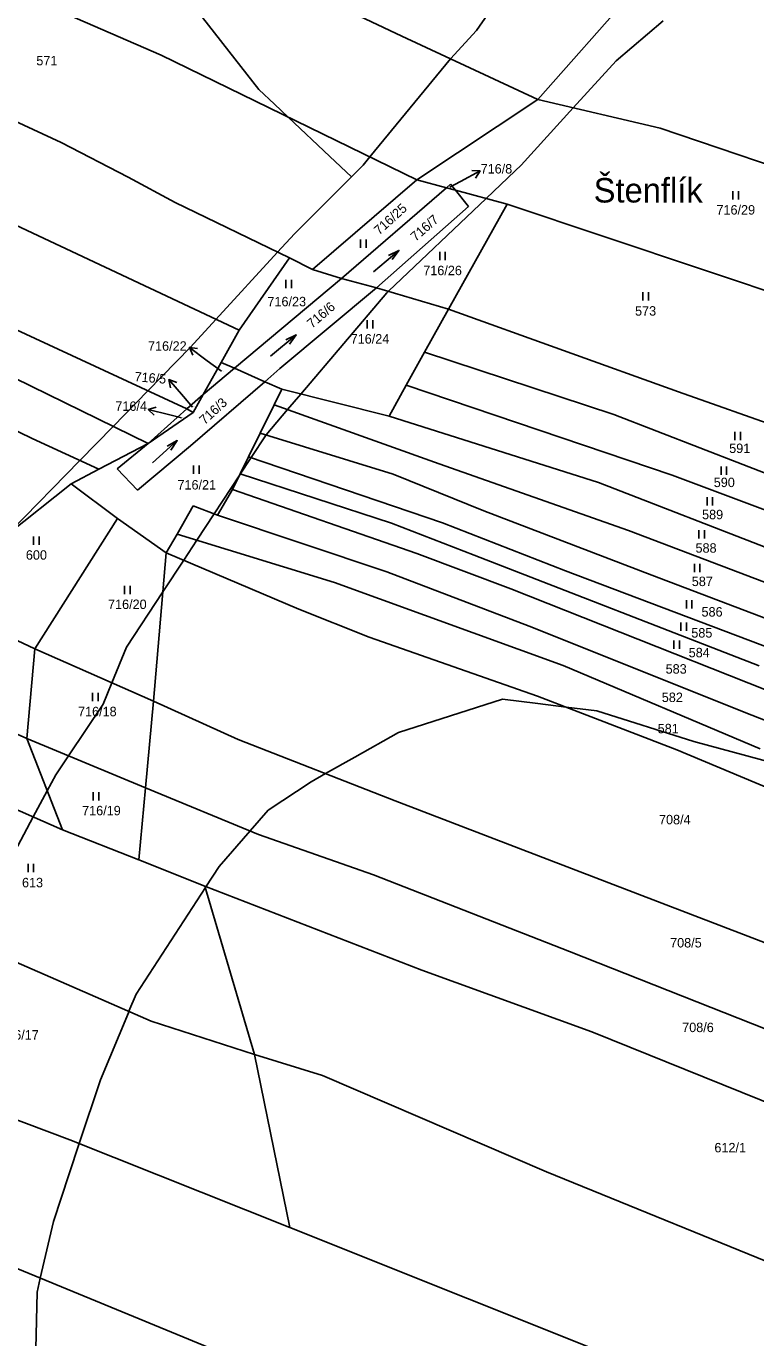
# Model space of a CAD drawing. Extents: x -749173 to -746119, y -1132678 to -1130338.
# Drawn here: x -748430.5 to -748299.2, y -1131207.1 to -1130971 of the extents above; entities that cross this region are included whole.
import ezdxf

# ---------------------------------------------------------------- set-up
doc = ezdxf.new("R2010")
doc.units = 0
for name, color, linetype in [('Vrstva 1', 7, 'Continuous'), ('Vrstva 15', 7, 'Continuous'), ('Vrstva 16', 7, 'Continuous'), ('Vrstva 18', 7, 'Continuous'), ('Vrstva 25', 7, 'Continuous'), ('Vrstva 52', 7, 'Continuous'), ('Vrstva 6', 7, 'Continuous')]:
    doc.layers.add(name, color=color, linetype=linetype)

msp = doc.modelspace()

# ---------------------------------------------------------------- linework, layer by layer
at = {"layer": 'Vrstva 1'}
for points in [[(-748321.33, -1130964.79), (-748338.46, -1130984.21)], [(-748338.46, -1130984.21), (-748360.19, -1130998.63)], [(-748360.19, -1130998.63), (-748379, -1131014.81)], [(-748354.9, -1131000.06), (-748354.14, -1130999.4)], [(-748354.14, -1130999.4), (-748353.27, -1131000.5)], [(-748373.77, -1131016.38), (-748354.9, -1131000.06)], [(-748353.27, -1131000.5), (-748350.94, -1131003.46)], [(-748350.94, -1131003.46), (-748367.47, -1131018.07)], [(-748383.15, -1131012.7), (-748392.16, -1131025.73)], [(-748379, -1131014.81), (-748383.15, -1131012.7)], [(-748393.03, -1131032.57), (-748373.77, -1131016.38)], [(-748367.47, -1131018.07), (-748384.84, -1131032.61)], [(-748358.83, -1131029.64), (-748354.54, -1131021.9)], [(-748354.54, -1131021.9), (-748313.1, -1131036.82)], [(-748392.16, -1131025.73), (-748395.42, -1131031.51)], [(-748362.13, -1131035.6), (-748358.83, -1131029.64)], [(-748395.42, -1131031.51), (-748398.67, -1131037.3)], [(-748398.67, -1131037.3), (-748393.03, -1131032.57)], [(-748384.84, -1131032.61), (-748387.58, -1131034.98)], [(-748401.59, -1131039.86), (-748398.67, -1131037.3)], [(-748387.58, -1131034.98), (-748400.96, -1131046.55)], [(-748385.87, -1131039.12), (-748384.5, -1131036.34)], [(-748384.5, -1131036.34), (-748365.22, -1131041.21)], [(-748365.22, -1131041.21), (-748362.13, -1131035.6)], [(-748313.1, -1131036.82), (-748275.09, -1131050.22)], [(-748388.38, -1131044.22), (-748385.87, -1131039.12)], [(-748408.58, -1131046.09), (-748401.59, -1131039.86)], [(-748390.49, -1131048.5), (-748388.38, -1131044.22)], [(-748417.45, -1131050.74), (-748408.58, -1131046.09)], [(-748414.17, -1131050.66), (-748408.58, -1131046.09)], [(-748400.96, -1131046.55), (-748410.47, -1131054.51)], [(-748392.02, -1131051.59), (-748390.49, -1131048.5)], [(-748422.44, -1131053.36), (-748417.45, -1131050.74)], [(-748410.47, -1131054.51), (-748414.17, -1131050.66)], [(-748433.86, -1131062.5), (-748422.44, -1131053.36)], [(-748393.4, -1131054.38), (-748392.02, -1131051.59)], [(-748393.4, -1131054.38), (-748396.09, -1131058.99)], [(-748360.23, -1131065.88), (-748393.4, -1131054.38)], [(-748400.45, -1131057.32), (-748403.37, -1131062.41)], [(-748396.09, -1131058.99), (-748400.45, -1131057.32)], [(-748403.37, -1131062.41), (-748405.3, -1131065.79)], [(-748405.3, -1131065.79), (-748407.59, -1131092.49)], [(-748343.3, -1131072.28), (-748360.23, -1131065.88)], [(-748277.63, -1131098.3), (-748343.3, -1131072.28)], [(-748407.59, -1131092.49), (-748409.03, -1131108.09)], [(-748409.03, -1131108.09), (-748410.22, -1131121.04)], [(-748410.22, -1131121.04), (-748398.34, -1131125.81)], [(-748398.34, -1131125.81), (-748389.42, -1131156.09)], [(-748389.42, -1131156.09), (-748383.08, -1131187.24)], [(-748422.65, -1131171.45), (-748446.57, -1131162.45)], [(-748383.08, -1131187.24), (-748422.65, -1131171.45)]]:
    msp.add_lwpolyline(points, dxfattribs=at)
at = {"layer": 'Vrstva 16'}
for p, q in [((-748350.34, -1130996.99), (-748348.84, -1130997.04)), ((-748400.55, -1131030.19), (-748401.15, -1131028.81)), ((-748404.55, -1131036.08), (-748404.83, -1131034.61)), ((-748407.46, -1131041.03), (-748408.54, -1131039.99))]:
    msp.add_line(p, q, dxfattribs=at)
for points in [[(-748352.37, -1130998.93), (-748348.84, -1130997.04), (-748349.64, -1130998.32)], [(-748354.3, -1130999.96), (-748352.37, -1130998.93)], [(-748397.94, -1131031.2), (-748401.15, -1131028.81), (-748399.66, -1131028.98)], [(-748395.38, -1131033.11), (-748397.94, -1131031.2)], [(-748402.22, -1131037.64), (-748404.83, -1131034.61), (-748403.41, -1131035.1)], [(-748404.66, -1131040.96), (-748408.54, -1131039.99), (-748407.1, -1131039.58)], [(-748400.57, -1131039.56), (-748402.22, -1131037.64)], [(-748402.56, -1131041.48), (-748404.66, -1131040.96)]]:
    msp.add_lwpolyline(points, dxfattribs=at)
at = {"layer": 'Vrstva 25'}
for p, q in [((-748303.33, -1131000.7), (-748303.33, -1131002.2)), ((-748302.33, -1131002.2), (-748302.33, -1131000.7)), ((-748370.35, -1131009.4), (-748370.35, -1131010.9)), ((-748369.35, -1131010.9), (-748369.35, -1131009.4)), ((-748368.04, -1131015.2), (-748363.44, -1131011.34)), ((-748356.1, -1131011.61), (-748356.1, -1131013.11)), ((-748355.1, -1131013.11), (-748355.1, -1131011.61)), ((-748383.76, -1131016.66), (-748383.76, -1131018.16)), ((-748382.76, -1131018.16), (-748382.76, -1131016.66)), ((-748319.53, -1131018.89), (-748319.53, -1131020.39)), ((-748318.53, -1131020.39), (-748318.53, -1131018.89)), ((-748369.16, -1131023.92), (-748369.16, -1131025.42)), ((-748368.16, -1131025.42), (-748368.16, -1131023.92)), ((-748386.53, -1131030.38), (-748381.93, -1131026.54)), ((-748302.98, -1131044), (-748302.98, -1131045.5)), ((-748301.98, -1131045.5), (-748301.98, -1131044)), ((-748407.8, -1131049.61), (-748403.34, -1131045.59)), ((-748400.39, -1131050.06), (-748400.39, -1131051.56)), ((-748399.39, -1131051.56), (-748399.39, -1131050.06)), ((-748305.46, -1131050.24), (-748305.46, -1131051.74)), ((-748304.46, -1131051.74), (-748304.46, -1131050.24)), ((-748307.98, -1131055.79), (-748307.98, -1131057.29)), ((-748306.98, -1131057.29), (-748306.98, -1131055.79)), ((-748429.2, -1131062.82), (-748429.2, -1131064.32)), ((-748428.2, -1131064.32), (-748428.2, -1131062.82)), ((-748309.46, -1131061.7), (-748309.46, -1131063.2)), ((-748308.46, -1131063.2), (-748308.46, -1131061.7)), ((-748310.27, -1131067.76), (-748310.27, -1131069.26)), ((-748309.27, -1131069.26), (-748309.27, -1131067.76)), ((-748412.81, -1131071.7), (-748412.81, -1131073.2)), ((-748411.81, -1131073.2), (-748411.81, -1131071.7)), ((-748311.7, -1131074.29), (-748311.7, -1131075.79)), ((-748310.7, -1131075.79), (-748310.7, -1131074.29)), ((-748312.69, -1131078.31), (-748312.69, -1131079.81)), ((-748311.69, -1131079.81), (-748311.69, -1131078.31)), ((-748313.95, -1131081.56), (-748313.95, -1131083.06)), ((-748312.95, -1131083.06), (-748312.95, -1131081.56)), ((-748418.58, -1131091), (-748418.58, -1131092.5)), ((-748417.58, -1131092.5), (-748417.58, -1131091)), ((-748418.44, -1131108.84), (-748418.44, -1131110.34)), ((-748417.44, -1131110.34), (-748417.44, -1131108.84)), ((-748430.17, -1131121.79), (-748430.17, -1131123.29)), ((-748429.17, -1131123.29), (-748429.17, -1131121.79))]:
    msp.add_line(p, q, dxfattribs=at)
for points in [[(-748365.29, -1131012.24), (-748363.44, -1131011.34), (-748364.65, -1131013.01)], [(-748383.78, -1131027.44), (-748381.93, -1131026.54), (-748383.14, -1131028.2)], [(-748405.16, -1131046.56), (-748403.34, -1131045.59), (-748404.49, -1131047.3)]]:
    msp.add_lwpolyline(points, dxfattribs=at)
at = {"layer": 'Vrstva 52'}
for points in [[(-748318.87, -1130852.62), (-748321.87, -1130851.37), (-748321.5, -1130856.35), (-748320.75, -1130866.43), (-748320.12, -1130874.75), (-748320.05, -1130879.41), (-748319.86, -1130891.82), (-748319.69, -1130902.87), (-748319.91, -1130904.61), (-748320.52, -1130909.26), (-748320.56, -1130909.62), (-748321.95, -1130914.57), (-748324.37, -1130923.25), (-748325.44, -1130926.45), (-748328.62, -1130936), (-748329.29, -1130937.4), (-748337.12, -1130953.87), (-748339.41, -1130957.17), (-748349.5, -1130971.75), (-748354.17, -1130976.86), (-748368.65, -1130994.51), (-748369.87, -1130996), (-748372, -1130998.12)], [(-748431.12, -1130928), (-748414.3, -1130949.53), (-748388.62, -1130982.37), (-748385.85, -1130985), (-748383.38, -1130987.35), (-748375.86, -1130994.47), (-748372, -1130998.12)], [(-748438.81, -1131131.25), (-748429.24, -1131113.33), (-748426.73, -1131108.63), (-748425.19, -1131105.75), (-748422.9, -1131102.32), (-748416.69, -1131093), (-748415.11, -1131089.18), (-748412.44, -1131082.75), (-748405.9, -1131072.8), (-748402.17, -1131067.12), (-748399.8, -1131063.51), (-748396.68, -1131058.76), (-748392.18, -1131051.91), (-748391.98, -1131051.6), (-748390.04, -1131048.65), (-748387.32, -1131044.52), (-748383.47, -1131039.98), (-748381.1, -1131037.2), (-748365.62, -1131019), (-748365.32, -1131018.71), (-748347.74, -1131002), (-748342.54, -1130997.05), (-748341.44, -1130996), (-748332.07, -1130985.7), (-748324.37, -1130977.25), (-748315.87, -1130970)], [(-748372, -1130998.12), (-748382.25, -1131008.37), (-748385.27, -1131011.67), (-748396.36, -1131023.76), (-748400.94, -1131028.75), (-748408.61, -1131036.61), (-748414.86, -1131043.02), (-748420.86, -1131049.17), (-748433.25, -1131061.87), (-748433.56, -1131062.26), (-748435.04, -1131064.1), (-748444.46, -1131075.78), (-748449.41, -1131081.91), (-748455.63, -1131089.62), (-748460.06, -1131095.12), (-748468.1, -1131102.73), (-748480.27, -1131116.82), (-748486.18, -1131123.66), (-748489.81, -1131127.87)], [(-748429, -1131219.25), (-748428.56, -1131198.87), (-748427.98, -1131196.35), (-748425.62, -1131186.12), (-748422.77, -1131177.56), (-748420.96, -1131172.12), (-748417.12, -1131160.62), (-748412.13, -1131148.57), (-748412.02, -1131148.31), (-748410.75, -1131145.25), (-748398.27, -1131126.04), (-748398.17, -1131125.88), (-748395.81, -1131122.25), (-748390.2, -1131115.85), (-748386.94, -1131112.12), (-748379.25, -1131107), (-748376.64, -1131105.53), (-748371.36, -1131102.55), (-748363.5, -1131098.12), (-748344.81, -1131092.12), (-748338.42, -1131092.92), (-748333.35, -1131093.56), (-748327.81, -1131094.25), (-748310.37, -1131099.75), (-748283.94, -1131106.87)]]:
    msp.add_lwpolyline(points, dxfattribs=at)
at = {"layer": 'Vrstva 6'}
for points in [[(-748391.2, -1130959.35), (-748362.89, -1130972.76)], [(-748406.22, -1130976.23), (-748433.55, -1130964.26)], [(-748464.62, -1130973.2), (-748424.22, -1130991.94)], [(-748362.89, -1130972.76), (-748338.46, -1130984.21)], [(-748360.19, -1130998.63), (-748406.22, -1130976.23)], [(-748316.44, -1130989.36), (-748338.46, -1130984.21)], [(-748284.95, -1131000.02), (-748316.44, -1130989.36)], [(-748424.22, -1130991.94), (-748412.15, -1130998.16)], [(-748412.15, -1130998.16), (-748403.69, -1131002.73)], [(-748354.9, -1131000.06), (-748360.19, -1130998.63)], [(-748353.27, -1131000.5), (-748354.9, -1131000.06)], [(-748343.93, -1131003.03), (-748353.27, -1131000.5)], [(-748482.79, -1131002.25), (-748401.59, -1131039.86)], [(-748392.16, -1131025.73), (-748440.48, -1131003.02)], [(-748403.69, -1131002.73), (-748383.15, -1131012.7)], [(-748343.93, -1131003.03), (-748354.54, -1131021.9)], [(-748291.24, -1131020.69), (-748343.93, -1131003.03)], [(-748373.77, -1131016.38), (-748379, -1131014.81)], [(-748367.47, -1131018.07), (-748373.77, -1131016.38)], [(-748354.54, -1131021.9), (-748367.47, -1131018.07)], [(-748408.58, -1131046.09), (-748444.76, -1131028.43)], [(-748324.79, -1131040.88), (-748358.83, -1131029.64)], [(-748393.03, -1131032.57), (-748395.42, -1131031.51)], [(-748387.58, -1131034.98), (-748393.03, -1131032.57)], [(-748398.67, -1131037.3), (-748400.45, -1131040.5)], [(-748384.5, -1131036.34), (-748387.58, -1131034.98)], [(-748362.13, -1131035.6), (-748314.24, -1131051.8)], [(-748443.17, -1131038.57), (-748429.46, -1131045.22)], [(-748385.87, -1131039.12), (-748356.17, -1131049.78)], [(-748400.45, -1131040.5), (-748408.58, -1131046.09)], [(-748400.45, -1131040.5), (-748401.59, -1131039.86)], [(-748327.49, -1131053.12), (-748365.22, -1131041.21)], [(-748278.3, -1131058.9), (-748324.79, -1131040.88)], [(-748364.47, -1131051.6), (-748388.38, -1131044.22)], [(-748429.46, -1131045.22), (-748417.45, -1131050.74)], [(-748390.49, -1131048.5), (-748355.58, -1131060.36)], [(-748356.17, -1131049.78), (-748322.13, -1131061.79)], [(-748414.11, -1131059.62), (-748422.44, -1131053.36)], [(-748364.77, -1131060.43), (-748392.02, -1131051.59)], [(-748348.15, -1131058.2), (-748364.47, -1131051.6)], [(-748295.64, -1131065.48), (-748327.49, -1131053.12)], [(-748314.24, -1131051.8), (-748271.86, -1131067.7)], [(-748317.94, -1131069.78), (-748348.15, -1131058.2)], [(-748414.11, -1131059.62), (-748428.96, -1131083.09)], [(-748405.3, -1131065.79), (-748414.11, -1131059.62)], [(-748365.59, -1131069.23), (-748396.09, -1131058.99)], [(-748349.88, -1131066.18), (-748364.77, -1131060.43)], [(-748355.58, -1131060.36), (-748333.47, -1131069.02)], [(-748403.37, -1131062.41), (-748375.02, -1131071.11)], [(-748322.13, -1131061.79), (-748250.9, -1131088.82)], [(-748381.45, -1131075.94), (-748405.3, -1131065.79)], [(-748298.6, -1131086.14), (-748349.88, -1131066.18)], [(-748339.97, -1131078.96), (-748365.59, -1131069.23)], [(-748333.47, -1131069.02), (-748293.98, -1131083.95)], [(-748269.91, -1131088.03), (-748317.94, -1131069.78)], [(-748375.02, -1131071.11), (-748333.85, -1131086.07)], [(-748428.96, -1131083.09), (-748443.88, -1131076.03)], [(-748381.45, -1131075.94), (-748368.77, -1131080.97)], [(-748299.92, -1131094.99), (-748339.97, -1131078.96)], [(-748368.77, -1131080.97), (-748338.48, -1131091.58)], [(-748430.39, -1131099.21), (-748428.96, -1131083.09)], [(-748428.96, -1131083.09), (-748407.59, -1131092.49)], [(-748333.85, -1131086.07), (-748298.42, -1131101.04)], [(-748430.39, -1131099.21), (-748451.45, -1131089.82)], [(-748313.45, -1131101.22), (-748338.48, -1131091.58)], [(-748392.37, -1131099.36), (-748407.59, -1131092.49)], [(-748255.06, -1131112.5), (-748299.92, -1131094.99)], [(-748424, -1131115.63), (-748457.53, -1131100.91)], [(-748409.03, -1131108.09), (-748430.39, -1131099.21)], [(-748430.39, -1131099.21), (-748424, -1131115.63)], [(-748364.1, -1131110.45), (-748392.37, -1131099.36)], [(-748284.62, -1131113.32), (-748313.45, -1131101.22)], [(-748388.71, -1131116.46), (-748409.03, -1131108.09)], [(-748289.57, -1131139.04), (-748364.1, -1131110.45)], [(-748424, -1131115.63), (-748410.22, -1131121.04)], [(-748367.99, -1131123.74), (-748388.71, -1131116.46)], [(-748332.74, -1131137.52), (-748367.99, -1131123.74)], [(-748359.3, -1131140.91), (-748398.34, -1131125.81)], [(-748261.74, -1131165.6), (-748332.74, -1131137.52)], [(-748408.02, -1131150.06), (-748432.29, -1131139.48)], [(-748328.73, -1131151.99), (-748359.3, -1131140.91)], [(-748389.42, -1131156.09), (-748408.02, -1131150.06)], [(-748250.95, -1131183.36), (-748328.73, -1131151.99)], [(-748377.21, -1131159.87), (-748389.42, -1131156.09)], [(-748336.88, -1131177.2), (-748377.21, -1131159.87)], [(-748290.63, -1131196.06), (-748336.88, -1131177.2)], [(-748383.08, -1131187.24), (-748319.11, -1131212.79)], [(-748396.53, -1131209.32), (-748445.77, -1131189.01)]]:
    msp.add_lwpolyline(points, dxfattribs=at)

# ---------------------------------------------------------------- texts
at = {"layer": 'Vrstva 15'}
msp.add_text('Štenflík', height=4.4, dxfattribs=at).set_placement((-748328.39, -1131002.73))
at = {"layer": 'Vrstva 16'}
for s, p in [('716/8', (-748348.73, -1130997.51)), ('716/22', (-748408.59, -1131029.41)), ('716/4', (-748414.47, -1131040.23))]:
    msp.add_text(s, height=1.7, dxfattribs=at).set_placement(p)
msp.add_text('716/5', height=1.7, rotation=355.4451, dxfattribs=at).set_placement((-748411.06, -1131034.9))
at = {"layer": 'Vrstva 18'}
for s, height, p in [('571', 1.7, (-748428.69, -1130978.04)), ('716/8', 0.1, (-748354.3, -1130999.96)), ('716/29', 1.7, (-748306.29, -1131004.9)), ('716/26', 1.7, (-748359.06, -1131015.81)), ('716/23', 1.7, (-748387.1, -1131021.41)), ('573', 1.7, (-748320.94, -1131023.09)), ('716/24', 1.7, (-748372.12, -1131028.12)), ('716/22', 0.1, (-748395.38, -1131033.11)), ('716/5', 0.1, (-748400.57, -1131039.56)), ('716/4', 0.1, (-748402.56, -1131041.48)), ('591', 1.7, (-748304, -1131047.82)), ('716/21', 1.7, (-748403.29, -1131054.39)), ('590', 1.7, (-748306.78, -1131053.95)), ('589', 1.7, (-748308.88, -1131059.74)), ('600', 1.7, (-748430.57, -1131067.02)), ('588', 1.7, (-748310.06, -1131065.76)), ('587', 1.7, (-748310.73, -1131071.77)), ('716/20', 1.7, (-748415.79, -1131075.9)), ('586', 1.7, (-748308.98, -1131077.26)), ('585', 1.7, (-748310.82, -1131081.04)), ('584', 1.7, (-748311.29, -1131084.59)), ('583', 1.7, (-748315.44, -1131087.53)), ('582', 1.7, (-748316.13, -1131092.64)), ('716/18', 1.7, (-748421.19, -1131095.2)), ('581', 1.7, (-748316.87, -1131098.27)), ('716/19', 1.7, (-748420.45, -1131113.03)), ('708/4', 1.7, (-748316.63, -1131114.65)), ('613', 1.7, (-748431.27, -1131125.99)), ('708/5', 1.7, (-748314.63, -1131136.82)), ('708/6', 1.7, (-748312.46, -1131152.05)), ('716/17', 1.7, (-748435.2, -1131153.4)), ('612/1', 1.7, (-748306.66, -1131173.7))]:
    msp.add_text(s, height=height, dxfattribs=at).set_placement(p)
for s, rotation, p in [('716/25', 42.2134, (-748366.98, -1131008.67)), ('716/7', 41.1656, (-748360.42, -1131009.81)), ('716/6', 40.4153, (-748379.08, -1131025.45)), ('716/3', 42.5309, (-748398.39, -1131042.81))]:
    msp.add_text(s, height=1.7, rotation=rotation, dxfattribs=at).set_placement(p)

doc.saveas('drawing.dxf')
